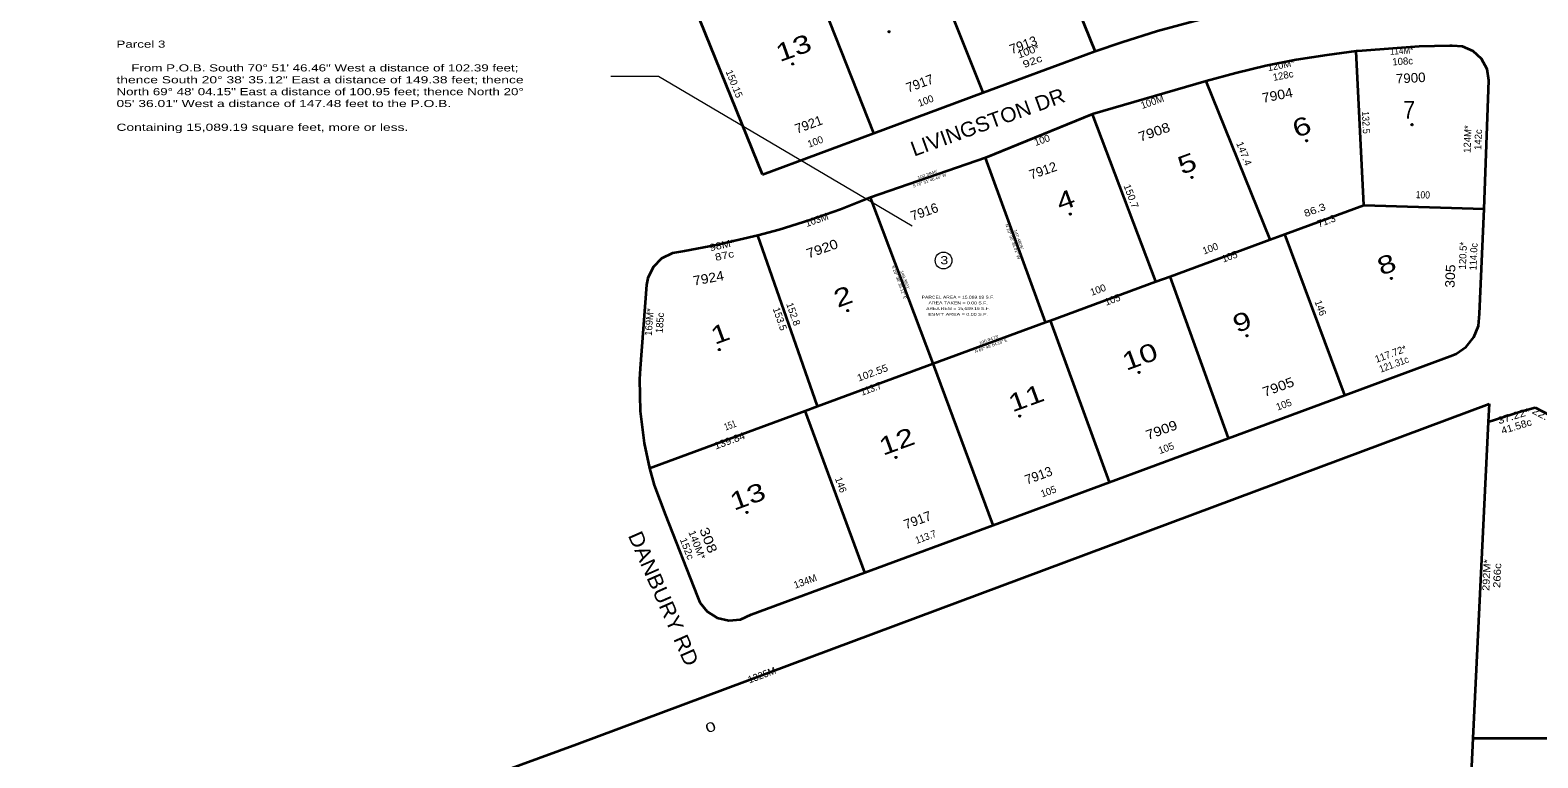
# Model space of a CAD drawing. Extents: x 2546959 to 2550387, y 581906 to 585027.
# Drawn here: x 2546959 to 2548228, y 583358 to 583970 of the extents above; entities that cross this region are included whole.
import ezdxf
from ezdxf.enums import TextEntityAlignment as Align

# ---------------------------------------------------------------- set-up
doc = ezdxf.new("R2010")
doc.units = 0
doc.header["$LTSCALE"] = 2.4
doc.header["$PDMODE"] = 32
doc.header["$PDSIZE"] = 1.2
for name, color, linetype, lineweight in [('1', 7, 'Continuous', 13), ('23', 7, 'Continuous', 13), ('40', 7, 'Continuous', 35), ('47', 7, 'Continuous', 13)]:
    doc.layers.add(name, color=color, linetype=linetype, lineweight=lineweight)
for name, color, linetype in [('20', 7, 'Continuous'), ('38', 7, 'Continuous'), ('39', 7, 'Continuous'), ('41', 7, 'Continuous'), ('42', 7, 'Continuous')]:
    doc.layers.add(name, color=color, linetype=linetype)

msp = doc.modelspace()

# ---------------------------------------------------------------- linework, layer by layer
at = {"layer": '1'}
msp.add_lwpolyline([(2547701.213, 583805.306), (2547487.622, 583931.445), (2547447.459, 583931.445)], dxfattribs=at)
at = {"layer": '23'}
msp.add_circle((2547727.697, 583776.562), 7.061, dxfattribs=at)
at = {"layer": '40'}
for p, q in [((2547668.847, 583883.672), (2547613.66, 584023.54)), ((2547761.113, 583917.857), (2547847.926, 583950.022)), ((2547847.926, 583950.022), (2547855.466, 583952.653)), ((2548081.692, 583823.179), (2548075.091, 583952.616)), ((2548182.892, 583820.016), (2548186.775, 583928.069)), ((2547668.847, 583883.672), (2547761.113, 583917.857)), ((2547948.711, 583927.52), (2547853.11, 583899.636)), ((2547948.836, 583927.554), (2547948.711, 583927.52)), ((2548002.792, 583794.151), (2547948.836, 583927.554)), ((2547853.11, 583899.636), (2547763.012, 583863.08)), ((2547906.568, 583758.75), (2547853.11, 583899.636)), ((2547575.211, 583848.979), (2547668.847, 583883.672)), ((2547763.012, 583863.08), (2547666.276, 583829.512)), ((2547813.679, 583724.576), (2547763.012, 583863.08)), ((2547718.94, 583689.721), (2547666.276, 583829.512)), ((2548014.971, 583798.632), (2548081.692, 583823.179)), ((2548081.692, 583823.179), (2548182.892, 583820.016)), ((2548179.03, 583731.77), (2548182.892, 583820.016)), ((2547621.476, 583653.864), (2547571.179, 583797.638)), ((2548002.792, 583794.151), (2548014.971, 583798.632)), ((2548065.549, 583663.105), (2548014.971, 583798.632)), ((2547906.568, 583758.75), (2547918.458, 583763.125)), ((2547477.488, 583756.191), (2547472.221, 583685.75)), ((2547813.679, 583724.576), (2547817.869, 583726.118)), ((2547718.94, 583689.721), (2547813.679, 583724.576)), ((2547621.476, 583653.864), (2547718.94, 583689.721)), ((2547769.401, 583553.845), (2547718.94, 583689.721)), ((2548065.549, 583663.105), (2548154.407, 583695.887)), ((2547967.597, 583626.967), (2548065.549, 583663.105)), ((2547418.933, 583369.569), (2548187.133, 583655.923)), ((2547479.989, 583601.811), (2547611.293, 583650.118)), ((2548213.399, 583649.463), (2548225.941, 583652.934)), ((2548225.941, 583652.934), (2548244.139, 583643.253)), ((2548186.209, 583640.677), (2548173.506, 583374.598)), ((2547867.433, 583590.013), (2547967.597, 583626.967)), ((2547769.401, 583553.845), (2547867.433, 583590.013)), ((2547493.52, 583562.139), (2547520.143, 583494.249)), ((2547661.372, 583513.99), (2547769.401, 583553.845)), ((2547565.755, 583478.713), (2547661.372, 583513.99)), ((2548173.506, 583374.598), (2548322.179, 583374.593))]:
    msp.add_line(p, q, dxfattribs=at)
for points in [[(2547855.466, 583952.653), (2547799.804, 584090.124), (2547898.743, 584125.514)], [(2547761.113, 583917.857), (2547705.757, 584056.483), (2547799.804, 584090.124)], [(2547575.211, 583848.979), (2547518.285, 583989.423), (2547613.638, 584023.531)], [(2547855.466, 583952.653), (2547877.689, 583960.409), (2547907.788, 583969.778), (2547938.188, 583978.118), (2547958.685, 583982.997)], [(2548154.105, 583957.155), (2548128.089, 583956.591), (2548080.091, 583953.111), (2548075.091, 583952.616)], [(2548186.775, 583928.069), (2548185.364, 583937.675), (2548180.829, 583946.259), (2548173.688, 583952.838), (2548164.762, 583956.655), (2548156.105, 583957.261), (2548154.105, 583957.155)], [(2548075.091, 583952.616), (2548050.377, 583949.486), (2548024.689, 583945.323), (2547999.162, 583940.271), (2547973.825, 583934.333), (2547948.836, 583927.554)], [(2547666.276, 583829.512), (2547640.921, 583819.526), (2547615.206, 583810.504), (2547589.169, 583802.46), (2547571.179, 583797.638)], [(2547571.179, 583797.638), (2547536.277, 583789.348), (2547509.499, 583784.299)], [(2547967.597, 583626.967), (2547918.458, 583763.125), (2548002.792, 583794.151)], [(2547509.499, 583784.299), (2547499.408, 583782.797), (2547490.312, 583778.176), (2547483.147, 583770.913), (2547478.651, 583761.756), (2547477.488, 583756.191)], [(2547867.433, 583590.013), (2547817.869, 583726.118), (2547906.568, 583758.75)], [(2548154.407, 583695.887), (2548159.407, 583697.982), (2548167.687, 583703.792), (2548174.141, 583711.881), (2548178.029, 583721.471), (2548179.03, 583731.77)], [(2547472.221, 583685.75), (2547471.769, 583676.718), (2547472.253, 583649.6), (2547475.491, 583622.673), (2547479.989, 583601.811)], [(2547661.372, 583513.99), (2547611.293, 583650.118), (2547621.476, 583653.864)], [(2548187.133, 583655.923), (2548186.209, 583640.677), (2548213.399, 583649.463)], [(2547479.989, 583601.811), (2547484.033, 583587.548), (2547493.52, 583562.139)], [(2547520.143, 583494.249), (2547522.524, 583488.757), (2547528.747, 583480.995), (2547537.166, 583475.698), (2547546.855, 583473.446), (2547556.749, 583474.49), (2547565.755, 583478.713)], [(2547325.615, 582599.385), (2546958.539, 583201.411), (2547418.933, 583369.569)], [(2548173.506, 583374.598), (2548167.788, 583254.805), (2548326.552, 583260.472)]]:
    msp.add_lwpolyline(points, dxfattribs=at)
at = {"layer": '41'}
for p in [(2547681.827, 583969.099), (2547600.708, 583942.059), (2548122.189, 583890.878), (2548033.343, 583877.358), (2547936.773, 583846.455), (2547834.408, 583815.552), (2548104.805, 583761.473), (2547647.06, 583734.432), (2547983.126, 583713.187), (2547538.902, 583701.597), (2547892.35, 583682.284), (2547791.916, 583645.586), (2547687.62, 583610.82), (2547562.078, 583564.466)]:
    msp.add_point(p, dxfattribs=at)
at = {"layer": '47'}
msp.add_lwpolyline([(2547763.012, 583863.08), (2547666.276, 583829.512), (2547718.939, 583689.721), (2547813.679, 583724.576)], close=True, dxfattribs=at)

# ---------------------------------------------------------------- texts
at = {"layer": '1'}
for s, width, p in [('Parcel 3', 1.4, (2547031.231, 583955.663)), ('    From P.O.B. South 70° 51\' 46.46" West a distance of 102.39 feet;', 1.4, (2547031.231, 583935.663)), ('thence South 20° 38\' 35.12" East a distance of 149.38 feet; thence', 1.45, (2547031.231, 583925.663)), ('North 69° 48\' 04.15" East a distance of 100.95 feet; thence North 20°', 1.4, (2547031.231, 583915.663)), ('05\' 36.01" West a distance of 147.48 feet to the P.O.B.', 1.45, (2547031.231, 583905.663)), ('Containing 15,089.19 square feet, more or less.', 1.45, (2547031.231, 583885.663))]:
    msp.add_text(s, height=6, dxfattribs=dict(at, width=width)).set_placement(p)
at = {"layer": '20'}
for s, rotation, width, p in [('LIVINGSTON DR', 19.906, 1.05, (2547767.029, 583887.177)), ('DANBURY RD', 293.728, 1.1, (2547486.187, 583489.47))]:
    msp.add_text(s, height=12.5, rotation=rotation, dxfattribs=dict(at, width=width)).set_placement(p, align=Align.CENTER)
at = {"layer": '23'}
for s, rotation, width, p in [("102.3946'", 19.137, 1.25, (2547714.546, 583847.85)), ('S 70° 51\' 46.46" W', 19.137, 1.1, (2547716.314, 583842.749)), ('N 20° 05\' 36.01" W', 290.093, 1.15, (2547784.833, 583792.077)), ("147.4805'", 290.093, 1.25, (2547789.905, 583793.931)), ('S 20° 38\' 35.12" E', 290.643, 1.15, (2547689.119, 583757.819)), ("149.3821'", 290.643, 1.2, (2547694.171, 583759.722)), ("100.9473'", 20.199, 1.25, (2547766.205, 583708.709)), ('N 69° 48\' 04.15" E', 20.199, 1.1, (2547768.069, 583703.641))]:
    msp.add_text(s, height=2.399, rotation=rotation, dxfattribs=dict(at, width=width)).set_placement(p, align=Align.CENTER)
for s, height, width, p in [('3', 6.845, 1.3, (2547728.302, 583773.37)), ('PARCEL AREA = 15,089.19 S.F.', 2.399, 1.3, (2547739.977, 583744.451)), ('AREA REM = 15,089.19 S.F.', 2.399, 1.3, (2547739.976, 583734.852)), ('AREA TAKEN = 0.00 S.F.', 2.399, 1.35, (2547739.977, 583739.651)), ("ESM'T AREA = 0.00 S.F.", 2.399, 1.4, (2547739.976, 583730.052))]:
    msp.add_text(s, height=height, dxfattribs=dict(at, width=width)).set_placement(p, align=Align.CENTER)
at = {"layer": '38', "width": 1.35}
for s, rotation, p in [('13', 19.682, (2547603.869, 583948.506)), ('6', 20.199, (2548031.859, 583882.141)), ('5', 20.199, (2547935.327, 583851.208)), ('4', 20.199, (2547832.929, 583820.381)), ('8', 20.199, (2548103.325, 583766.302)), ('2', 20.199, (2547645.571, 583739.208)), ('9', 20.199, (2547981.673, 583717.983)), ('1', 20.199, (2547542.069, 583708.067)), ('10', 20.199, (2547895.556, 583688.764)), ('11', 20.199, (2547799.733, 583653.783)), ('12', 20.199, (2547690.813, 583617.297)), ('13', 20.199, (2547565.268, 583571.004))]:
    msp.add_text(s, height=15, rotation=rotation, dxfattribs=at).set_placement(p, align=Align.CENTER)
at = {"layer": '38', "width": 0.9}
msp.add_text('7', height=15, dxfattribs=at).set_placement((2548119.708, 583895.878), align=Align.CENTER)
at = {"layer": '39'}
for s, rotation, p in [('7913', 20.33, (2547796.214, 583954.242)), ('7917', 20.33, (2547709.014, 583921.922)), ('7921', 20.33, (2547615.459, 583887.299)), ('7912', 19.137, (2547812.732, 583848.495)), ('7916', 19.137, (2547712.84, 583813.829)), ('7913', 20.251, (2547809.053, 583591.896)), ('7917', 20.251, (2547707.19, 583554.35))]:
    msp.add_text(s, height=8, rotation=rotation, dxfattribs=at).set_placement(p, align=Align.CENTER)
for s, rotation, width, p in [('7900', 3.231, 1.05, (2548121.298, 583926.17)), ('7904', 11.196, 1.1, (2548009.548, 583911.767)), ('7908', 19.138, 1.15, (2547906.3, 583880.96)), ('7920', 19.333, 1.15, (2547626.756, 583782.735)), ('7924', 10.678, 1.1, (2547530.497, 583757.72)), ('305', 87.494, 1.1, (2548158.395, 583763.22)), ('7905', 20.251, 1.15, (2548010.923, 583666.431)), ('7909', 20.251, 1.15, (2547912.579, 583630.165)), ('308', 291.412, 1.25, (2547525.971, 583539.711)), ('0', 20.443, 1.45, (2547532.928, 583380.047))]:
    msp.add_text(s, height=8, rotation=rotation, dxfattribs=dict(at, width=width)).set_placement(p, align=Align.CENTER)
at = {"layer": '42'}
for s, rotation, width, p in [('100*', 20.33, 1.15, (2547800.133, 583949.815)), ('114M*', 3.288, 0.85, (2548113.56, 583950.199)), ('92c', 20.33, 1.3, (2547803.58, 583941.414)), ('132.5', 272.92, 0.95, (2548080.405, 583892.606)), ('147.4', 292.021, 1.05, (2547977.959, 583865.462)), ('150.7', 290.779, 1.05, (2547882.903, 583829.602)), ('100', 358.21, 0.9, (2548131.193, 583828.852)), ('86.3', 20.199, 1.2, (2548041.271, 583816.181)), ('98M*', 12.203, 1.15, (2547541.915, 583786.593)), ('114.0c', 87.494, 0.95, (2548176.94, 583779.674)), ('87c', 12.203, 1.25, (2547543.834, 583777.847)), ('102.55', 20.199, 1.1, (2547668.867, 583679.198)), ('121.31c', 20.251, 0.9, (2548107.944, 583686.513)), ('113.7', 20.199, 0.9, (2547667.606, 583665.84)), ('37.22*', 17.144, 1.2, (2548208.644, 583642.798)), ('22.6', 331.989, 1.25, (2548231.249, 583643.699)), ('151', 20.199, 0.7, (2547549.004, 583635.104)), ('41.58c', 17.144, 1.1, (2548210.95, 583634.153)), ('139.84', 20.199, 1.1, (2547548.497, 583622.024)), ('140M*', 291.412, 1.1, (2547517.345, 583536.138)), ('113.7', 20.251, 0.9, (2547713.743, 583541.151)), ('152c', 291.412, 1.1, (2547508.918, 583532.938)), ('292M*', 87.267, 1.15, (2548187.905, 583511.632)), ('266c', 87.267, 1.2, (2548196.865, 583511.204))]:
    msp.add_text(s, height=5.999, rotation=rotation, dxfattribs=dict(at, width=width)).set_placement(p, align=Align.CENTER)
for s, rotation, p in [('120M*', 11.196, (2548012.473, 583938.06)), ('108c', 3.288, (2548114.471, 583941.261)), ('150.15', 292.064, (2547548.707, 583924.154)), ('128c', 11.196, (2548014.181, 583929.314)), ('100', 20.33, (2547713.681, 583908.215)), ('100M', 19.138, (2547904.439, 583907.305)), ('124M*', 87.942, (2548171.892, 583878.611)), ('100', 20.33, (2547620.723, 583873.762)), ('100', 19.137, (2547811.585, 583875.09)), ('142c', 87.942, (2548180.851, 583878.184)), ('103M', 19.333, (2547621.901, 583808.007)), ('71.3', 20.199, (2548051.155, 583806.984)), ('100', 20.199, (2547953.343, 583783.838)), ('120.5*', 87.494, (2548167.997, 583780.478)), ('105', 20.199, (2547969.557, 583777.011)), ('100', 20.199, (2547858.785, 583749.065)), ('152.8', 289.282, (2547598.409, 583730.483)), ('105', 20.199, (2547870.998, 583740.744)), ('146', 290.465, (2548042.355, 583735.592)), ('169M*', 85.724, (2547482.826, 583724.477)), ('185c', 85.724, (2547491.787, 583723.838)), ('153.5', 289.282, (2547587.103, 583726.43)), ('117.72*', 20.251, (2548105.206, 583695.177)), ('105', 20.251, (2548015.267, 583652.428)), ('105', 20.251, (2547916.176, 583615.842)), ('146', 290.198, (2547638.453, 583586.713)), ('105', 20.251, (2547817.084, 583579.362)), ('134M', 20.251, (2547612.234, 583503.735)), ('1325M', 20.302, (2547575.705, 583424.805))]:
    msp.add_text(s, height=5.999, rotation=rotation, dxfattribs=at).set_placement(p, align=Align.CENTER)

doc.saveas('drawing.dxf')
